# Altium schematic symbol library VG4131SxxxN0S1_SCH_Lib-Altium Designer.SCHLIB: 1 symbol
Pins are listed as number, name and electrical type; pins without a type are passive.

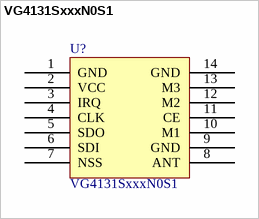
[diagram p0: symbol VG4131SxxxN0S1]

## VG4131SxxxN0S1
designator U?
footprint G55xxNS1-Mult
pins: 1 GND, 2 VCC, 3 IRQ, 4 CLK, 5 SDO, 6 SDI, 7 NSS, 8 ANT, 9 GND, 10 M1, 11 CE, 12 M2, 13 M3, 14 GND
